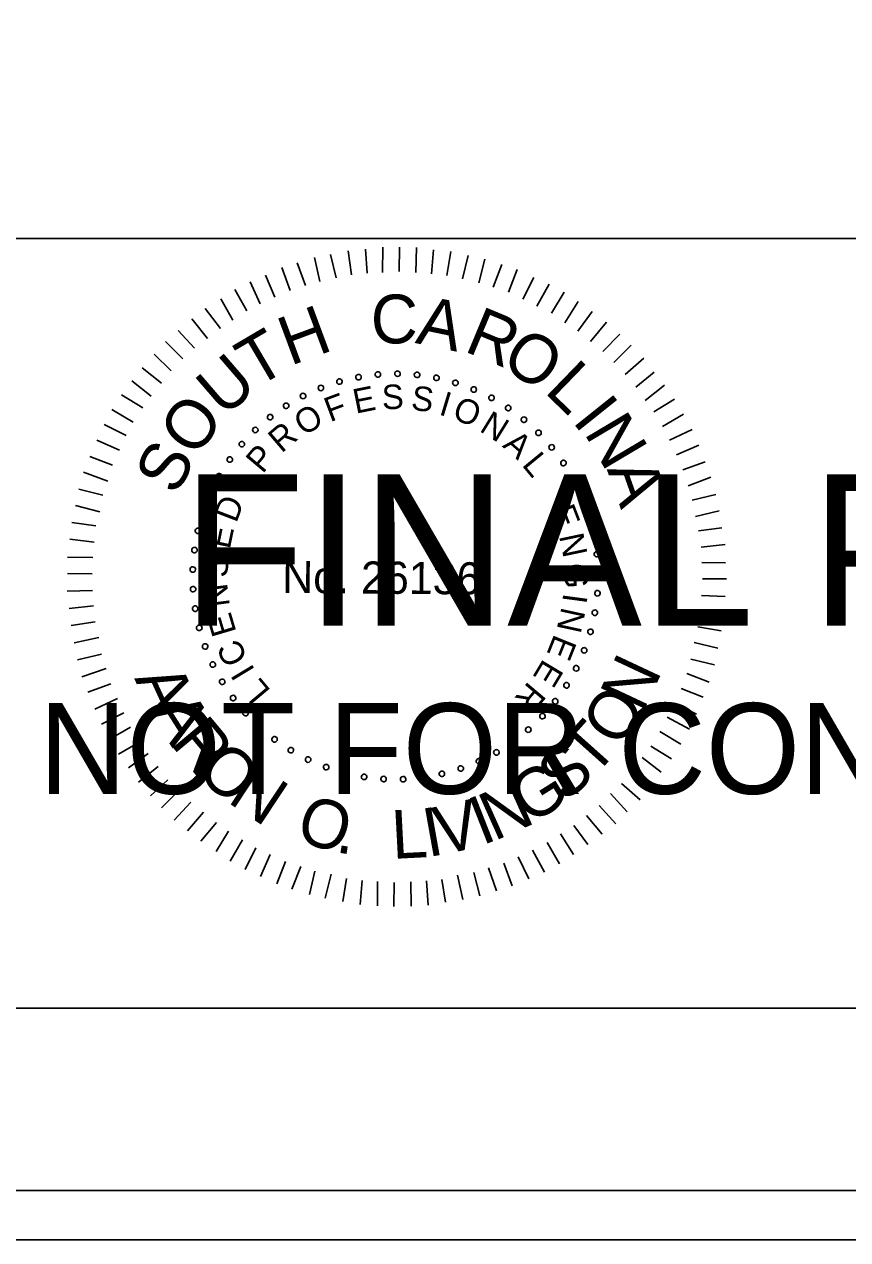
# Model space of a CAD drawing. Extents: x 967 to 1326, y 964 to 2584.
# Drawn here: x 1170.56 to 1189.3, y 1523.72 to 1551.36 of the extents above; entities that cross this region are included whole.
import ezdxf

# ---------------------------------------------------------------- set-up
doc = ezdxf.new("R2010")
doc.units = 0
for name, color, linetype in [('RD_SHT_Misc1', 7, 'Continuous'), ('RD_SHT_Misc2', 7, 'Continuous'), ('RD_XS_ExPaveRet', 7, 'Continuous'), ('RD_XS_TX_Elev_EX', 7, 'Continuous')]:
    doc.layers.add(name, color=color, linetype=linetype)

msp = doc.modelspace()

# ---------------------------------------------------------------- linework, layer by layer
at = {"layer": 'RD_SHT_Misc1'}
for p, q in [((1178.01, 1545.663), (1177.93, 1546.209)), ((1178.364, 1545.699), (1178.33, 1546.244)), ((1178.717, 1545.719), (1178.722, 1546.295)), ((1179.093, 1545.739), (1179.098, 1546.292)), ((1179.469, 1545.713), (1179.489, 1546.288)), ((1179.829, 1545.687), (1179.872, 1546.231)), ((1180.174, 1545.646), (1180.271, 1546.19)), ((1176.964, 1545.419), (1176.769, 1545.935)), ((1177.287, 1545.508), (1177.169, 1546.054)), ((1177.657, 1545.597), (1177.53, 1546.128)), ((1180.535, 1545.573), (1180.662, 1546.102)), ((1180.902, 1545.478), (1181.045, 1546.022)), ((1181.231, 1545.384), (1181.428, 1545.896)), ((1176.264, 1545.156), (1176.053, 1545.657)), ((1176.61, 1545.306), (1176.423, 1545.83)), ((1181.584, 1545.265), (1181.78, 1545.786)), ((1175.933, 1545.005), (1175.699, 1545.506)), ((1181.905, 1545.109), (1182.154, 1545.606)), ((1182.226, 1544.953), (1182.506, 1545.45)), ((1175.308, 1544.634), (1175.036, 1545.12)), ((1175.624, 1544.846), (1175.352, 1545.332)), ((1182.562, 1544.789), (1182.85, 1545.27)), ((1175.03, 1544.445), (1174.681, 1544.9)), ((1182.86, 1544.572), (1183.163, 1545.053)), ((1183.158, 1544.378), (1183.484, 1544.828)), ((1174.729, 1544.217), (1174.372, 1544.665)), ((1183.447, 1544.145), (1183.811, 1544.587)), ((1174.435, 1543.997), (1174.062, 1544.399)), ((1183.729, 1543.92), (1184.116, 1544.316)), ((1174.172, 1543.753), (1173.776, 1544.148)), ((1183.98, 1543.672), (1184.368, 1544.061)), ((1173.909, 1543.479), (1173.52, 1543.858)), ((1184.232, 1543.394), (1184.657, 1543.767)), ((1173.684, 1543.197), (1173.242, 1543.546)), ((1184.475, 1543.108), (1184.892, 1543.45)), ((1173.451, 1542.9), (1173.009, 1543.256)), ((1184.687, 1542.807), (1185.128, 1543.156)), ((1173.257, 1542.64), (1172.776, 1542.936)), ((1173.039, 1542.312), (1172.559, 1542.6)), ((1184.885, 1542.544), (1185.355, 1542.832)), ((1185.081, 1542.213), (1185.56, 1542.493)), ((1172.883, 1542.006), (1172.379, 1542.256)), ((1185.24, 1541.904), (1185.756, 1542.145)), ((1172.727, 1541.677), (1172.215, 1541.904)), ((1185.399, 1541.573), (1185.907, 1541.791)), ((1172.571, 1541.333), (1172.051, 1541.53)), ((1185.549, 1541.226), (1186.057, 1541.414)), ((1172.461, 1540.974), (1171.91, 1541.178)), ((1185.669, 1540.865), (1186.185, 1541.06)), ((1172.351, 1540.652), (1171.807, 1540.787)), ((1185.759, 1540.541), (1186.297, 1540.667)), ((1172.286, 1540.276), (1171.727, 1540.419)), ((1185.832, 1540.165), (1186.371, 1540.298)), ((1172.191, 1539.955), (1171.647, 1540.029)), ((1185.906, 1539.842), (1186.436, 1539.906)), ((1172.15, 1539.587), (1171.598, 1539.653)), ((1185.964, 1539.473), (1186.51, 1539.53)), ((1172.124, 1539.234), (1171.548, 1539.239)), ((1185.977, 1539.12), (1186.514, 1539.115)), ((1172.105, 1538.866), (1171.545, 1538.871)), ((1185.997, 1538.751), (1186.542, 1538.747)), ((1172.118, 1538.482), (1171.542, 1538.471)), ((1185.971, 1538.368), (1186.508, 1538.348)), ((1172.138, 1538.136), (1171.585, 1538.072)), ((1185.952, 1538.022), (1186.497, 1537.949)), ((1172.173, 1537.768), (1171.627, 1537.688)), ((1185.888, 1537.655), (1186.417, 1537.566)), ((1172.262, 1537.414), (1171.701, 1537.296)), ((1185.808, 1537.302), (1186.345, 1537.175)), ((1172.321, 1537.037), (1171.774, 1536.911)), ((1185.729, 1536.926), (1186.265, 1536.792)), ((1172.425, 1536.707), (1171.871, 1536.519)), ((1185.634, 1536.597), (1186.146, 1536.401)), ((1172.53, 1536.36), (1172.007, 1536.173)), ((1185.508, 1536.253), (1186.013, 1536.057)), ((1172.681, 1536.029), (1172.165, 1535.788)), ((1172.831, 1535.705), (1172.323, 1535.441)), ((1185.352, 1535.924), (1185.857, 1535.675)), ((1185.188, 1535.603), (1185.7, 1535.33)), ((1172.982, 1535.374), (1172.497, 1535.094)), ((1185.024, 1535.274), (1185.498, 1534.987)), ((1173.194, 1535.042), (1172.709, 1534.762)), ((1184.822, 1534.946), (1185.288, 1534.658)), ((1173.384, 1534.78), (1172.936, 1534.453)), ((1184.62, 1534.687), (1185.055, 1534.353)), ((1173.612, 1534.478), (1173.164, 1534.129)), ((1184.403, 1534.389), (1184.814, 1534.033)), ((1173.832, 1534.177), (1173.437, 1533.812)), ((1184.155, 1534.092), (1184.574, 1533.72)), ((1174.091, 1533.945), (1173.689, 1533.541)), ((1183.899, 1533.864), (1184.28, 1533.454)), ((1174.35, 1533.674), (1173.97, 1533.263)), ((1183.644, 1533.597), (1184.024, 1533.18)), ((1174.64, 1533.442), (1174.275, 1533.022)), ((1174.937, 1533.209), (1174.58, 1532.782)), ((1183.358, 1533.37), (1183.715, 1532.944)), ((1175.212, 1533.014), (1174.932, 1532.549)), ((1182.764, 1532.952), (1183.059, 1532.482)), ((1183.065, 1533.141), (1183.384, 1532.709)), ((1175.525, 1532.812), (1175.245, 1532.331)), ((1175.83, 1532.633), (1175.588, 1532.136)), ((1182.463, 1532.755), (1182.743, 1532.269)), ((1176.159, 1532.477), (1175.94, 1531.98)), ((1181.8, 1532.431), (1182.041, 1531.93)), ((1182.124, 1532.581), (1182.396, 1532.08)), ((1176.503, 1532.321), (1176.307, 1531.816)), ((1176.855, 1532.211), (1176.651, 1531.69)), ((1177.177, 1532.1), (1177.05, 1531.572)), ((1181.122, 1532.175), (1181.31, 1531.652)), ((1181.476, 1532.28), (1181.664, 1531.771)), ((1177.545, 1532.036), (1177.409, 1531.484)), ((1177.897, 1531.933), (1177.808, 1531.412)), ((1178.25, 1531.892), (1178.207, 1531.34)), ((1178.603, 1531.866), (1178.598, 1531.313)), ((1178.978, 1531.84), (1178.974, 1531.295)), ((1179.355, 1531.86), (1179.365, 1531.307)), ((1179.715, 1531.88), (1179.749, 1531.327)), ((1180.061, 1531.915), (1180.149, 1531.393)), ((1180.423, 1532.012), (1180.541, 1531.458)), ((1180.791, 1532.07), (1180.926, 1531.54))]:
    msp.add_line(p, q, dxfattribs=at)
for centre, start, end in [((1178.609, 1543.397), 5.0653, 185.0653), ((1179.055, 1543.414), 359.5268, 179.5268), ((1179.055, 1543.414), 179.5268, 359.5268), ((1179.5, 1543.388), 353.9884, 173.9884), ((1177.312, 1543.091), 21.6807, 201.6807), ((1177.734, 1543.235), 16.1422, 196.1422), ((1177.734, 1543.235), 196.1422, 16.1422), ((1178.168, 1543.337), 10.6038, 190.6038), ((1178.168, 1543.337), 190.6038, 10.6038), ((1178.609, 1543.397), 185.0653, 5.0653), ((1179.5, 1543.388), 173.9884, 353.9884), ((1179.94, 1543.319), 168.4499, 348.4499), ((1179.94, 1543.319), 348.4499, 168.4499), ((1180.372, 1543.208), 162.9114, 342.9114), ((1180.372, 1543.208), 342.9114, 162.9114), ((1176.906, 1542.908), 27.2191, 207.2191), ((1176.906, 1542.908), 207.2191, 27.2191), ((1177.312, 1543.091), 201.6807, 21.6807), ((1180.79, 1543.056), 157.373, 337.373), ((1180.79, 1543.056), 337.373, 157.373), ((1181.193, 1542.864), 151.8345, 331.8345), ((1181.193, 1542.864), 331.8345, 151.8345), ((1176.52, 1542.686), 32.7576, 212.7576), ((1176.52, 1542.686), 212.7576, 32.7576), ((1181.574, 1542.634), 146.2961, 326.2961), ((1181.574, 1542.634), 326.2961, 146.2961), ((1176.156, 1542.428), 38.2961, 218.2961), ((1176.156, 1542.428), 218.2961, 38.2961), ((1181.932, 1542.368), 140.7576, 320.7576), ((1181.932, 1542.368), 320.7576, 140.7576), ((1175.82, 1542.135), 43.8345, 223.8345), ((1175.82, 1542.135), 223.8345, 43.8345), ((1182.263, 1542.069), 135.2191, 315.2191), ((1182.263, 1542.069), 315.2191, 135.2191), ((1175.513, 1541.812), 49.373, 229.373), ((1175.513, 1541.812), 229.373, 49.373), ((1182.563, 1541.74), 129.6807, 309.6807), ((1182.563, 1541.74), 309.6807, 129.6807), ((1175.239, 1541.461), 54.9114, 234.9114), ((1175.239, 1541.461), 234.9114, 54.9114), ((1182.83, 1541.383), 124.1422, 304.1422), ((1182.83, 1541.383), 304.1422, 124.1422), ((1175, 1541.085), 60.4499, 240.4499), ((1175, 1541.085), 240.4499, 60.4499), ((1183.061, 1541.002), 118.6038, 298.6038), ((1183.061, 1541.002), 298.6038, 118.6038), ((1174.798, 1540.687), 65.9884, 245.9884), ((1174.798, 1540.687), 245.9884, 65.9884), ((1183.255, 1540.601), 113.0653, 293.0653), ((1183.255, 1540.601), 293.0653, 113.0653), ((1174.636, 1540.272), 71.5268, 251.5268), ((1174.636, 1540.272), 251.5268, 71.5268), ((1183.408, 1540.182), 107.5268, 287.5268), ((1183.408, 1540.182), 287.5268, 107.5268), ((1174.514, 1539.843), 77.0653, 257.0653), ((1174.514, 1539.843), 257.0653, 77.0653), ((1183.521, 1539.751), 101.9884, 281.9884), ((1183.521, 1539.751), 281.9884, 101.9884), ((1174.435, 1539.405), 82.6038, 262.6038), ((1174.435, 1539.405), 262.6038, 82.6038), ((1183.592, 1539.311), 96.4499, 276.4499), ((1183.592, 1539.311), 276.4499, 96.4499), ((1174.398, 1538.961), 88.1422, 268.1422), ((1174.398, 1538.961), 268.1422, 88.1422), ((1183.619, 1538.866), 90.9114, 270.9114), ((1183.619, 1538.866), 270.9114, 90.9114), ((1174.404, 1538.515), 93.6807, 273.6807), ((1174.404, 1538.515), 273.6807, 93.6807), ((1183.604, 1538.421), 85.373, 265.373), ((1183.604, 1538.421), 265.373, 85.373), ((1174.453, 1538.072), 99.2191, 279.2191), ((1174.453, 1538.072), 279.2191, 99.2191), ((1183.546, 1537.979), 79.8345, 259.8345), ((1183.546, 1537.979), 259.8345, 79.8345), ((1174.545, 1537.636), 104.7576, 284.7576), ((1174.545, 1537.636), 284.7576, 104.7576), ((1183.445, 1537.545), 74.2961, 254.2961), ((1183.445, 1537.545), 254.2961, 74.2961), ((1174.678, 1537.211), 110.2961, 290.2961), ((1174.678, 1537.211), 290.2961, 110.2961), ((1183.303, 1537.122), 68.7576, 248.7576), ((1183.303, 1537.122), 248.7576, 68.7576), ((1174.852, 1536.8), 115.8345, 295.8345), ((1174.852, 1536.8), 295.8345, 115.8345), ((1183.121, 1536.716), 63.2191, 243.2191), ((1183.121, 1536.716), 243.2191, 63.2191), ((1175.065, 1536.409), 121.373, 301.373), ((1175.065, 1536.409), 301.373, 121.373), ((1182.9, 1536.328), 57.6807, 237.6807), ((1182.9, 1536.328), 237.6807, 57.6807), ((1175.314, 1536.039), 126.9114, 306.9114), ((1175.314, 1536.039), 306.9114, 126.9114), ((1182.643, 1535.964), 52.1422, 232.1422), ((1182.643, 1535.964), 232.1422, 52.1422), ((1175.598, 1535.696), 132.4499, 312.4499), ((1175.598, 1535.696), 312.4499, 132.4499), ((1182.353, 1535.627), 46.6038, 226.6038), ((1182.353, 1535.627), 226.6038, 46.6038), ((1175.914, 1535.381), 137.9884, 317.9884), ((1175.914, 1535.381), 317.9884, 137.9884), ((1176.258, 1535.099), 143.5268, 323.5268), ((1176.258, 1535.099), 323.5268, 143.5268), ((1182.03, 1535.319), 41.0653, 221.0653), ((1182.03, 1535.319), 221.0653, 41.0653), ((1176.629, 1534.851), 149.0653, 329.0653), ((1176.629, 1534.851), 329.0653, 149.0653), ((1181.305, 1534.803), 29.9884, 209.9884), ((1181.68, 1535.043), 35.5268, 215.5268), ((1181.68, 1535.043), 215.5268, 35.5268), ((1177.021, 1534.639), 154.6038, 334.6038), ((1177.021, 1534.639), 334.6038, 154.6038), ((1180.908, 1534.6), 24.4499, 204.4499), ((1180.908, 1534.6), 204.4499, 24.4499), ((1181.305, 1534.803), 209.9884, 29.9884), ((1177.432, 1534.467), 160.1422, 340.1422), ((1177.432, 1534.467), 340.1422, 160.1422), ((1177.858, 1534.335), 165.6807, 345.6807), ((1177.858, 1534.335), 345.6807, 165.6807), ((1178.294, 1534.245), 351.2191, 171.2191), ((1179.627, 1534.232), 7.8345, 187.8345), ((1180.065, 1534.313), 13.373, 193.373), ((1180.065, 1534.313), 193.373, 13.373), ((1180.494, 1534.436), 18.9114, 198.9114), ((1180.494, 1534.436), 198.9114, 18.9114), ((1178.294, 1534.245), 171.2191, 351.2191), ((1178.737, 1534.198), 356.7576, 176.7576), ((1178.737, 1534.198), 176.7576, 356.7576), ((1179.183, 1534.193), 2.2961, 182.2961), ((1179.183, 1534.193), 182.2961, 2.2961), ((1179.627, 1534.232), 187.8345, 7.8345)]:
    msp.add_arc(centre, 0.0627, start, end, dxfattribs=at)
at = {"layer": 'RD_XS_ExPaveRet'}
for points in [[(967.409, 1523.72), (1326.285, 1523.72), (1326.285, 1743.72), (967.409, 1743.72)], [(988.525, 1524.84), (1326.285, 1524.84), (1326.285, 1742.6), (988.525, 1742.6)]]:
    msp.add_lwpolyline(points, close=True, dxfattribs=at)
at = {"layer": 'RD_XS_TX_Elev_EX'}
for p, q in [((996.114, 1546.486), (1323.886, 1546.486)), ((1323.886, 1528.983), (996.114, 1528.983))]:
    msp.add_line(p, q, dxfattribs=at)

# ---------------------------------------------------------------- texts
at = {"layer": 'RD_SHT_Misc1'}
for s, height, rotation, p in [('C', 1.11, 359.5482, (1178.442, 1544.108)), ('A', 1.11, 348.1981, (1179.439, 1544.115)), ('H', 1.11, 20.3637, (1176.614, 1543.587)), ('R', 1.11, 337.4344, (1180.541, 1543.937)), ('T', 1.11, 30.4992, (1175.828, 1543.072)), ('O', 1.108, 326.5869, (1181.366, 1543.609)), ('U', 1.11, 40.8022, (1175.102, 1542.403)), ('L', 1.11, 315.9488, (1182.373, 1543.003)), ('E', 0.557, 11.4103, (1178.103, 1542.503)), ('S', 0.557, 2.208, (1178.709, 1542.601)), ('S', 0.557, 352.6608, (1179.346, 1542.599)), ('F', 0.557, 20.6127, (1177.52, 1542.309)), ('I', 0.557, 343.1136, (1179.975, 1542.491)), ('O', 0.557, 338.4392, (1180.274, 1542.401)), ('I', 1.11, 308.6613, (1183.011, 1542.338)), ('O', 1.11, 52.0267, (1174.435, 1541.474)), ('O', 0.557, 30.8477, (1176.917, 1541.987)), ('N', 0.557, 328.2042, (1180.896, 1542.12)), ('N', 1.11, 300.7037, (1183.285, 1542.075)), ('R', 0.557, 40.3949, (1176.415, 1541.594)), ('A', 0.557, 318.657, (1181.424, 1541.762)), ('S', 1.108, 63.2511, (1174.029, 1540.619)), ('P', 0.557, 49.9421, (1175.985, 1541.124)), ('L', 0.557, 309.4546, (1181.869, 1541.339)), ('A', 1.11, 289.4792, (1183.814, 1541.243)), ('D', 0.557, 69.0364, (1175.386, 1540.003)), ('E', 0.557, 291.049, (1182.53, 1540.307)), ('E', 0.557, 78.2388, (1175.238, 1539.407)), ('N', 0.557, 281.8466, (1182.728, 1539.726)), ('S', 0.557, 87.786, (1175.187, 1538.772)), ('No. 26136', 0.7311, 359.5268, (1176.429, 1538.43)), ('G', 0.557, 272.2995, (1182.833, 1539.097)), ('N', 0.557, 97.3332, (1175.242, 1538.137)), ('I', 0.557, 262.4084, (1182.83, 1538.437)), ('E', 0.557, 106.5355, (1175.394, 1537.541)), ('N', 0.557, 257.7339, (1182.789, 1538.127)), ('C', 0.557, 116.4266, (1175.661, 1536.938)), ('E', 0.557, 248.1867, (1182.628, 1537.511)), ('I', 0.557, 121.1011, (1175.823, 1536.67)), ('E', 0.557, 238.9844, (1182.378, 1536.949)), ('N', 1.105, 64.8922, (1184.632, 1535.684)), ('A', 1.105, 294.7297, (1173.062, 1536.486)), ('L', 0.557, 129.9595, (1176.187, 1536.204)), ('R', 0.557, 229.782, (1182.041, 1536.435)), ('O', 1.105, 56.2059, (1184.102, 1534.874)), ('A', 1.105, 302.2892, (1173.414, 1535.72)), ('R', 1.105, 309.8487, (1173.865, 1535.007)), ('T', 1.105, 48.2685, (1183.515, 1534.211)), ('O', 1.105, 317.7861, (1174.434, 1534.33)), ('S', 1.105, 40.3311, (1182.842, 1533.636)), ('N', 1.105, 326.4725, (1175.158, 1533.686)), ('G', 1.105, 32.0198, (1182.059, 1533.14)), ('N', 1.105, 24.0824, (1181.252, 1532.776)), ('O', 1.105, 342.3472, (1176.697, 1532.82)), ('V', 1.105, 12.7741, (1180.033, 1532.457)), ('I', 1.105, 21.4605, (1180.976, 1532.681)), ('L', 1.105, 2.9677, (1178.943, 1532.379)), ('I', 1.105, 10.1523, (1179.743, 1532.418)), ('.', 1.105, 351.0336, (1177.623, 1532.536))]:
    msp.add_text(s, height=height, rotation=rotation, dxfattribs=at).set_placement(p)
at = {"layer": 'RD_SHT_Misc2'}
for s, height, p in [('FINAL PLANS', 3.4375, (1174.145, 1537.685)), ('NOT FOR CONSTRUCTION', 2.0625, (1170.901, 1533.86))]:
    msp.add_text(s, height=height, dxfattribs=at).set_placement(p)

doc.saveas('drawing.dxf')
